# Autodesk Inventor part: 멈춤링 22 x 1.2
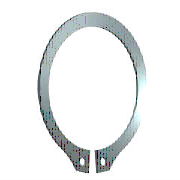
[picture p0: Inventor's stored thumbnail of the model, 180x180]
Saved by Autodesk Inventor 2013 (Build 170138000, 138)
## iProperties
IsCustomPart: 0
Created: 2015-11
Part Number: 멈춤링 22 x 1.2
Material: 스테인리스강
Description: 리테이닝 링(C형)
Document SubType Name: Modeling
Standard: KS B 1336
Designer: mdu
Standards Organization: KS
Language: ko-KR
Size Designation: 22 x 1.2
Categories: <MemberInstance><Categories><Category DisplayName="샤프트 부품" InternalName="7f7aeb1f-a693-4053-b835-cee3144e0d98" Mnemonic="SHFT"><Category DisplayName="써클립" Inter
Density: 1 g/cm^3
Author: mdu
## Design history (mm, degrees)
sketch "스케치1"
  geometry: L1 (-6, 0)-(6, 0) reference; L2 (0, 20.189)-(0, -80.536) reference; L3 (-48.09, 0)-(48.09, 0) reference; L4 (-0.5, -21.488)-(-0.5, -25.588); L5 (-0.5, -6.54)-(-0.5, -13.29); L6 (-2.795, 2.7)-(3.672, 2.7); L7 (0.5, -6.54)-(0.5, -13.29); L8 (0.5, -21.488)-(0.5, -25.588); C1 r 1 at (-2, -23.437); C2 r 1 at (2, -23.437); A1 r 10.5 centre (0, -11) between (0.5, -21.488) and (-0.5, -21.488); A2 r 13.025 centre (0, -10.325) between (5.149, -22.289) and (-5.149, -22.289); A3 r 14.597 centre (0, -11) between (-2.318, -25.411) and (-0.5, -25.588); A4 r 2 centre (-2, -23.437) between (-3.97, -23.781) and (-2.318, -25.411); A5 r 2 centre (-5.94, -24.126) between (-3.97, -23.781) and (-5.149, -22.289); A6 r 2 centre (5.94, -24.126) between (5.149, -22.289) and (3.97, -23.781); A7 r 2 centre (2, -23.437) between (2.318, -25.411) and (3.97, -23.781); A8 r 14.597 centre (0, -11) between (0.5, -25.588) and (2.318, -25.411)
  constraints: 16 point on circle, 12 end point, 10 centre point, 9 symmetric about line, 5 point on line, 4 tangent, 3 coincident, 2 horizontal, 1 perpendicular, 1 vertical, 5 other
  dimensions: "d0" = 21 diameter of A1 (= ND); "d1" = 4.1 distance of L4.end L4.start (= SRB2); "d6" = 0.5 distance between parallel lines of L2 L5 (= 0.25 x SD5); "d7" = 2.7 distance between parallel lines of L6 L3 (= SRB1); "d8" = 0.675 distance of A1.centre A2.centre (= 0.25 x SRB1); "d9" = 2 radius of A4 (= SD5); "d10" = 2 radius of A5 (= SD5); "d11" = 1.5 distance from line of L4 A4.centre (= 0.75 x SD5); "d12" = 2 diameter of C1 (= SD5); "d13" = 2 diameter of C2 (= SD5); "d14" = 11 distance from line of A1.centre L1 (= 0.5 x WD)
extrude "본체" new body sketch "스케치1" distance "d2" = 1.2 (= SD); taper "d3" = 0 deg
workaxis "Work Axis1"
workplane "Work Plane1"
body "Solid1"
other parameters: "WD" = 22 (= WDMIN) [user parameter; used in 1 equation term], "SD" = 1.2 [user parameter; used in 1 equation term], "SRB1" = 2.7 [user parameter; used in 2 equation terms], "ND" = 21 [user parameter; used in 1 equation term], "SRB2" = 4.1 [user parameter; used in 1 equation term], "SD5" = 2 [user parameter; used in 6 equation terms], "d15" = 0, "d16" = 0, "d17" = 0, "d41" = 0, "d42" = 0, "WDMIN" = 22 [user parameter; used in 1 equation term], "SD3" = 20.5 [user parameter], "WDMAX" = 24 [user parameter]
